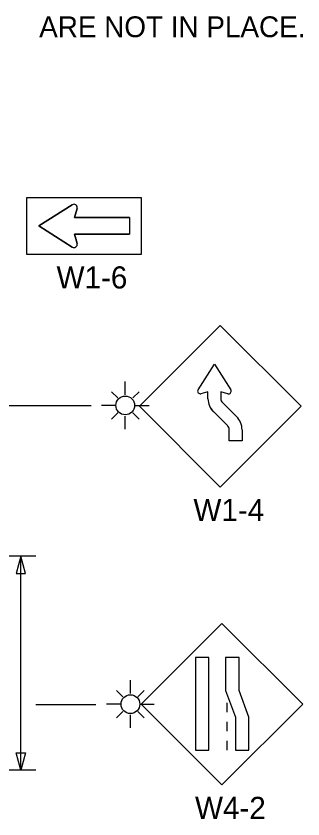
# Model space of a CAD drawing. Extents: x 16038 to 19504, y 5920 to 8321.
# Drawn here: x 17243.3 to 17339.6, y 7443.6 to 7713.6 of the extents above; entities that cross this region are included whole.
import ezdxf

# ---------------------------------------------------------------- set-up
doc = ezdxf.new("R2010")
doc.units = 0
doc.layers.add('TRAFFIC_SIGNS_PR', color=7, linetype='Continuous')
doc.layers.add('TYPICAL_TEXT_DIMEN_PR', color=7, linetype='Continuous')

msp = doc.modelspace()

# ---------------------------------------------------------------- linework, layer by layer
at = {"layer": 'TRAFFIC_SIGNS_PR'}
for p, q in [((17262.09, 7650.16), (17250.93, 7643.06)), ((17262.93, 7645.86), (17263.77, 7648.92)), ((17281.33, 7645.86), (17262.93, 7645.86)), ((17281.33, 7645.86), (17281.33, 7640.26)), ((17250.93, 7643.06), (17262.09, 7635.96)), ((17263.77, 7637.2), (17262.93, 7640.26)), ((17262.93, 7640.26), (17281.33, 7640.26)), ((17284.7, 7582.41), (17311.86, 7609.56)), ((17339.01, 7582.41), (17311.86, 7609.56)), ((17279.95, 7586.25), (17279.95, 7590.75)), ((17277.44, 7585.21), (17275.33, 7587.32)), ((17282.46, 7585.21), (17284.57, 7587.32)), ((17276.79, 7582.7), (17271.96, 7582.7)), ((17283.1, 7582.7), (17287.98, 7582.7)), ((17311.86, 7555.25), (17284.7, 7582.41)), ((17339.01, 7582.41), (17311.86, 7555.25)), ((17317.33, 7578.94), (17312.61, 7583.65)), ((17312.61, 7583.65), (17317.33, 7578.94)), ((17277.43, 7580.18), (17275.33, 7578.08)), ((17282.46, 7580.18), (17284.57, 7578.08)), ((17314.27, 7575.89), (17309.56, 7580.6)), ((17314.27, 7575.89), (17309.56, 7580.6)), ((17279.95, 7574.73), (17279.95, 7579.14)), ((17312.43, 7509.38), (17285.28, 7482.22)), ((17339.59, 7482.22), (17312.43, 7509.38)), ((17281.67, 7485.79), (17281.67, 7490.29)), ((17279.16, 7484.75), (17277.05, 7486.86)), ((17284.19, 7484.75), (17286.29, 7486.86)), ((17278.52, 7482.23), (17273.68, 7482.23)), ((17284.83, 7482.23), (17289.71, 7482.23)), ((17285.28, 7482.22), (17312.43, 7455.07)), ((17312.43, 7455.07), (17339.59, 7482.22)), ((17314.07, 7482.71), (17314.07, 7479.51)), ((17279.16, 7479.72), (17277.05, 7477.61)), ((17284.19, 7479.72), (17286.29, 7477.61)), ((17281.67, 7474.27), (17281.67, 7478.68)), ((17314.07, 7476.31), (17314.07, 7473.11)), ((17314.07, 7469.91), (17314.07, 7466.71))]:
    msp.add_line(p, q, dxfattribs=at)
for points in [[(17285.33, 7633.46), (17246.93, 7633.46), (17246.93, 7652.66), (17285.33, 7652.66)], [(17303.54, 7497.96), (17303.54, 7466.71), (17308.03, 7466.71), (17308.03, 7497.96)], [(17313.67, 7497.96), (17313.67, 7486.78), (17317.02, 7477.9), (17317.02, 7466.71), (17321.51, 7466.71), (17321.51, 7477.9), (17318.17, 7486.78), (17318.17, 7497.96)]]:
    msp.add_lwpolyline(points, close=True, dxfattribs=at)
for points in [[(17262.09, 7635.96), (17250.93, 7643.06), (17262.09, 7650.16)], [(17263.77, 7648.92), (17262.93, 7645.86), (17281.33, 7645.86), (17281.33, 7640.26), (17262.93, 7640.26), (17263.77, 7637.2)], [(17304.4, 7587.93), (17309.89, 7596.54), (17315.37, 7587.93)], [(17304.41, 7587.93), (17309.89, 7596.54), (17315.37, 7587.93)], [(17307.74, 7584.91), (17307.73, 7587.28), (17305.37, 7586.63)], [(17307.74, 7584.91), (17307.73, 7587.28), (17305.37, 7586.63)], [(17314.41, 7586.63), (17312.05, 7587.28), (17312.05, 7584.98)], [(17314.41, 7586.63), (17313.57, 7586.86), (17312.05, 7587.28), (17312.05, 7584.98)], [(17319.19, 7574.52), (17319.19, 7570.82), (17314.88, 7570.82), (17314.88, 7574.52)]]:
    msp.add_lwpolyline(points, dxfattribs=at)
for centre in [(17279.95, 7582.7), (17281.67, 7482.23)]:
    msp.add_circle(centre, 3.15, dxfattribs=at)
for centre, radius, start, end in [((17262.69, 7649.22), 1.12, 344.6731, 122.4696), ((17262.69, 7649.22), 1.12, 344.6731, 122.4696), ((17262.69, 7636.9), 1.12, 237.5304, 15.3269), ((17262.69, 7636.9), 1.12, 237.5304, 15.3269), ((17305.14, 7587.47), 0.866, 147.7292, 285.3172), ((17305.14, 7587.47), 0.866, 147.7196, 285.3201), ((17295.3, 7593.73), 10.8, 327.5335, 327.5431), ((17314.64, 7587.46), 0.866, 254.6148, 32.4712), ((17308.22, 7576.21), 10.8, 105.3192, 105.32), ((17313.9, 7584.98), 6.17, 180.6181, 225.7875), ((17313.9, 7584.98), 6.17, 180.6245, 225.2313), ((17313.9, 7584.98), 1.85, 180, 225.7875), ((17313.9, 7584.98), 1.85, 179.8762, 225.7877), ((17313.03, 7574.52), 6.17, 0, 45.7883), ((17313.03, 7574.52), 1.85, 0, 47.628)]:
    msp.add_arc(centre, radius, start, end, dxfattribs=at)
at = {"layer": 'TYPICAL_TEXT_DIMEN_PR'}
for p, q in [((17268.44, 7582.61), (17235.2, 7582.61)), ((17249.88, 7532.05), (17159.27, 7532.05)), ((17244.88, 7532.05), (17243.31, 7526.19)), ((17246.45, 7526.19), (17244.88, 7532.05)), ((17244.88, 7460.05), (17244.88, 7532.05)), ((17243.31, 7526.19), (17244.88, 7526.19)), ((17244.88, 7526.19), (17246.45, 7526.19)), ((17270.1, 7482.05), (17249.88, 7482.05)), ((17244.88, 7460.05), (17243.31, 7465.91)), ((17243.31, 7465.91), (17244.88, 7465.91)), ((17244.88, 7465.91), (17246.45, 7465.91)), ((17246.45, 7465.91), (17244.88, 7460.05)), ((17249.88, 7460.05), (17141.76, 7460.05))]:
    msp.add_line(p, q, dxfattribs=at)

# ---------------------------------------------------------------- texts
at = {"layer": 'TRAFFIC_SIGNS_PR'}
for s, height, p in [('ARE NOT IN PLACE.', 7, (17251.03, 7706.54)), ('W1-6', 7.44, (17256.87, 7622.02)), ('W1-4', 7.44, (17302.86, 7543.81)), ('W4-2', 7.44, (17303.39, 7443.63))]:
    msp.add_text(s, height=height, dxfattribs=at).set_placement(p)

doc.saveas('drawing.dxf')
